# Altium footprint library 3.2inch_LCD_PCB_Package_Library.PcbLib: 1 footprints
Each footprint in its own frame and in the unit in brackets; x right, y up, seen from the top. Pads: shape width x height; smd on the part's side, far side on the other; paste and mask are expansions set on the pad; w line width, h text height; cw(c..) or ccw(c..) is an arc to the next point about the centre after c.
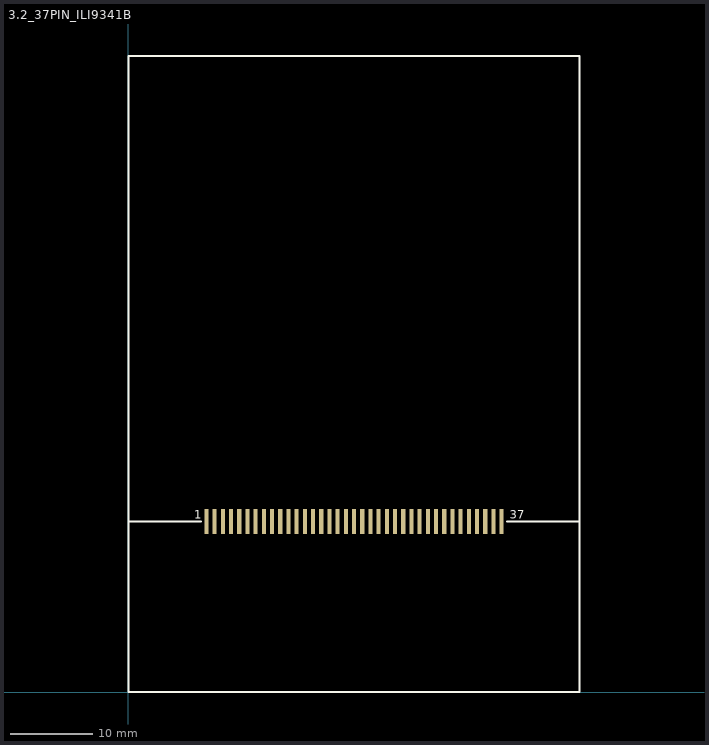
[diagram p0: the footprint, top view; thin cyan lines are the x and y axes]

## 3.2_37PIN_ILI9341B [mm]
pads (37):
  rect 0.5x3 smd: 1(9.503,20.815) 2(10.503,20.815) 3(11.503,20.815) 4(12.503,20.815) 5(13.503,20.815) 6(14.503,20.815) 7(15.503,20.815) 8(16.503,20.815) 9(17.503,20.815) 10(18.503,20.815) 11(19.503,20.815) 12(20.503,20.815) 13(21.503,20.815) 14(22.503,20.815) 15(23.503,20.815) 16(24.503,20.815) 17(25.503,20.815) 18(26.503,20.815) 19(27.503,20.815) 20(28.503,20.815) 21(29.503,20.815) 22(30.503,20.815) 23(31.503,20.815) 24(32.503,20.815) 25(33.503,20.815) 26(34.503,20.815) 27(35.503,20.815) 28(36.503,20.815) 29(37.503,20.815) 30(38.503,20.815) 31(39.503,20.815) 32(40.503,20.815) 33(41.503,20.815) 34(42.503,20.815) 35(43.503,20.815) 36(44.503,20.815) 37(45.503,20.815)
Top Overlay:
  lines w0.254: 0.127,20.8 8.829,20.8 ; 46.177,20.8 55,20.8 ; 0,0 0,77.6 55,77.6 55,0 0,0
  text "1" at 8.006,21.143 h1.02
  text "37" at 46.487,21.143 h1.02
